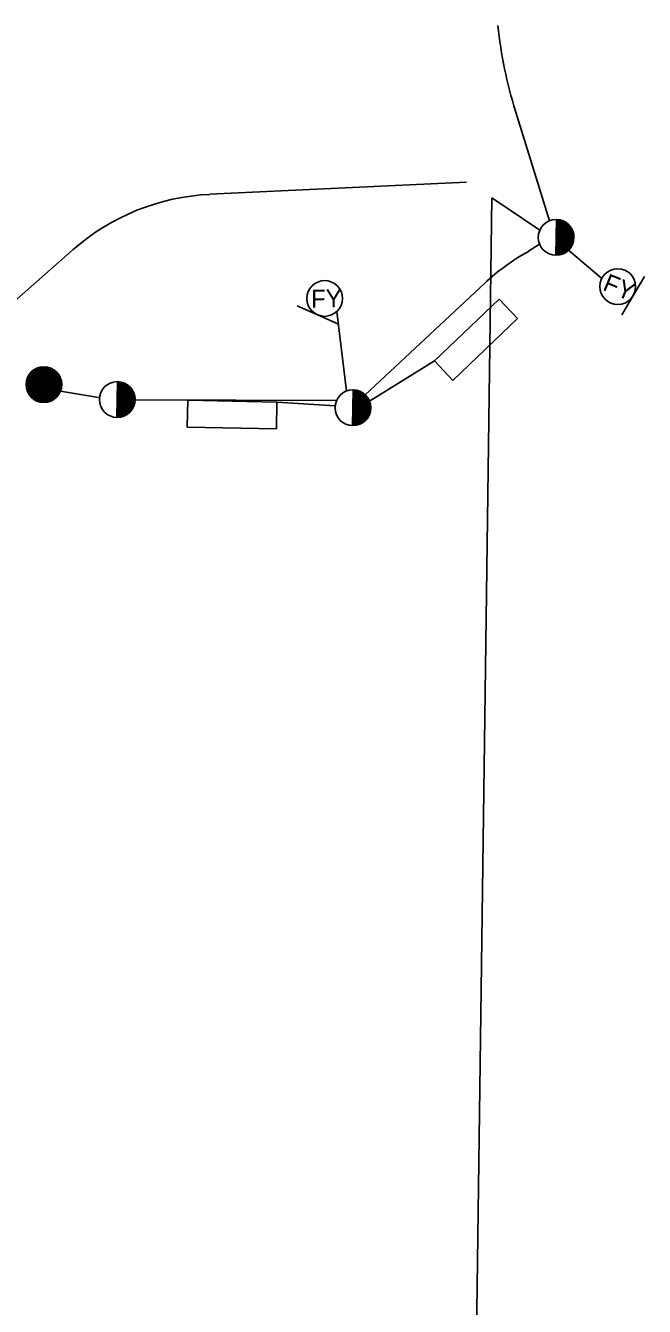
# Model space of a CAD drawing. Extents: x 584850 to 602551, y 145475 to 158627.
# Drawn here: x 585852.5 to 585991.1, y 152431.3 to 152717.9 of the extents above; entities that cross this region are included whole.
import ezdxf

# ---------------------------------------------------------------- set-up
doc = ezdxf.new("R2010")
doc.units = 0
doc.layers.add('Default', color=7, linetype='Continuous')

msp = doc.modelspace()

# ---------------------------------------------------------------- linework, layer by layer
at = {"layer": 'Default'}
for p, q in [((585969.85, 152674.27), (585962.21, 152698.81)), ((585893.76, 152680.19), (585951.25, 152682.9)), ((585953.46, 152423.71), (585956.91, 152679.38)), ((585967.65, 152672.15), (585956.91, 152679.38)), ((585971.39, 152674.55), (585971.24, 152666.55)), ((585971.32, 152671.23), (585973.83, 152673.64)), ((585971.33, 152671.57), (585973.64, 152673.8)), ((585971.34, 152672.25), (585973.22, 152674.05)), ((585971.34, 152671.91), (585973.43, 152673.93)), ((585971.35, 152672.59), (585973, 152674.17)), ((585971.36, 152673.27), (585972.5, 152674.36)), ((585971.36, 152672.93), (585972.75, 152674.27)), ((585971.37, 152673.6), (585972.23, 152674.43)), ((585975.2, 152669.62), (585971.37, 152673.6)), ((585971.38, 152674.28), (585971.64, 152674.53)), ((585971.38, 152673.94), (585971.94, 152674.49)), ((585975.29, 152670.22), (585971.38, 152674.28)), ((585975.25, 152669.92), (585971.38, 152673.94)), ((585971.39, 152674.55), (585971.39, 152674.55)), ((585971.39, 152674.55), (585971.39, 152674.55)), ((585975.3, 152670.56), (585971.46, 152674.54)), ((585975.29, 152670.92), (585971.83, 152674.51)), ((585975.22, 152671.34), (585972.24, 152674.43)), ((585975.1, 152671.81), (585972.72, 152674.28)), ((585974.83, 152672.44), (585973.34, 152673.98)), ((585971.24, 152666.82), (585975.29, 152670.72)), ((585971.25, 152667.5), (585975.22, 152671.32)), ((585971.25, 152667.16), (585975.28, 152671.04)), ((585971.26, 152667.84), (585975.17, 152671.6)), ((585971.27, 152668.51), (585974.99, 152672.09)), ((585971.27, 152668.17), (585975.08, 152671.85)), ((585971.28, 152668.85), (585974.89, 152672.33)), ((585971.29, 152669.53), (585974.64, 152672.76)), ((585971.29, 152669.19), (585974.76, 152672.54)), ((585971.3, 152669.87), (585974.5, 152672.95)), ((585971.31, 152670.55), (585974.19, 152673.32)), ((585971.31, 152670.21), (585974.34, 152673.14)), ((585971.32, 152670.89), (585974.01, 152673.49)), ((585974.4, 152668.03), (585971.32, 152671.23)), ((585974.25, 152667.84), (585971.32, 152670.89)), ((585974.55, 152668.22), (585971.33, 152671.57)), ((585974.81, 152668.65), (585971.34, 152672.25)), ((585974.69, 152668.42), (585971.34, 152671.91)), ((585974.93, 152668.87), (585971.35, 152672.59)), ((585975.12, 152669.37), (585971.36, 152673.27)), ((585975.03, 152669.11), (585971.36, 152672.93)), ((585833.35, 152641.7), (585863.13, 152667.83)), ((585972.35, 152666.7), (585971.26, 152667.84)), ((585972.85, 152666.88), (585971.27, 152668.51)), ((585972.62, 152666.77), (585971.27, 152668.17)), ((585973.09, 152666.98), (585971.28, 152668.85)), ((585973.51, 152667.23), (585971.29, 152669.53)), ((585973.31, 152667.09), (585971.29, 152669.19)), ((585973.72, 152667.36), (585971.3, 152669.87)), ((585974.08, 152667.68), (585971.31, 152670.55)), ((585973.9, 152667.52), (585971.31, 152670.21)), ((585971.32, 152666.56), (585975.3, 152670.4)), ((585971.69, 152666.58), (585975.26, 152670.02)), ((585972.09, 152666.64), (585975.21, 152669.64)), ((585972.56, 152666.75), (585975.05, 152669.15)), ((585973.17, 152667.01), (585974.75, 152668.54)), ((585971.48, 152666.57), (585971.24, 152666.82)), ((585971.28, 152666.55), (585971.24, 152666.6)), ((585972.08, 152666.64), (585971.25, 152667.5)), ((585971.8, 152666.59), (585971.25, 152667.16)), ((585974.09, 152667.67), (585981.55, 152661.37)), ((585986.03, 152653.2), (585991.09, 152661.83)), ((585944.05, 152642.9), (585958.52, 152656.71)), ((585958.52, 152656.71), (585962.66, 152652.37)), ((585913.27, 152655.25), (585922.41, 152651.2)), ((585924.32, 152636.15), (585922.19, 152653.95)), ((585948.19, 152638.56), (585962.66, 152652.37)), ((585944.05, 152642.9), (585929.5, 152633.89)), ((585944.05, 152642.9), (585948.19, 152638.56)), ((585852.56, 152637.62), (585856.39, 152641.61)), ((585852.58, 152637.29), (585856.72, 152641.6)), ((585852.58, 152637.99), (585856.02, 152641.57)), ((585852.61, 152636.98), (585857.03, 152641.58)), ((585852.62, 152638.38), (585855.62, 152641.5)), ((585852.67, 152636.7), (585857.32, 152641.53)), ((585852.74, 152636.42), (585857.59, 152641.47)), ((585852.76, 152638.87), (585855.16, 152641.37)), ((585852.83, 152636.17), (585857.85, 152641.4)), ((585858.24, 152634), (585852.87, 152639.16)), ((585852.94, 152635.93), (585858.09, 152641.3)), ((585858.46, 152634.12), (585852.98, 152639.38)), ((585853.03, 152639.5), (585854.55, 152641.08)), ((585853.05, 152635.7), (585858.32, 152641.2)), ((585858.68, 152634.25), (585853.09, 152639.61)), ((585853.18, 152635.49), (585858.54, 152641.08)), ((585858.89, 152634.38), (585853.22, 152639.82)), ((585853.31, 152635.28), (585858.75, 152640.94)), ((585859.07, 152634.53), (585853.36, 152640.01)), ((585853.46, 152635.09), (585858.95, 152640.81)), ((585859.26, 152634.69), (585853.5, 152640.21)), ((585853.62, 152634.91), (585859.14, 152640.66)), ((585859.43, 152634.85), (585853.67, 152640.38)), ((585853.78, 152634.74), (585859.31, 152640.49)), ((585859.59, 152635.04), (585853.84, 152640.55)), ((585853.97, 152634.58), (585859.49, 152640.33)), ((585859.74, 152635.22), (585854.02, 152640.71)), ((585854.16, 152634.43), (585859.64, 152640.14)), ((585859.88, 152635.42), (585854.22, 152640.85)), ((585854.35, 152634.28), (585859.79, 152639.95)), ((585860.01, 152635.63), (585854.42, 152640.99)), ((585854.56, 152634.16), (585859.93, 152639.75)), ((585860.13, 152635.84), (585854.64, 152641.12)), ((585854.78, 152634.04), (585860.05, 152639.53)), ((585860.23, 152636.08), (585854.87, 152641.23)), ((585855.01, 152633.93), (585860.17, 152639.31)), ((585860.32, 152636.33), (585855.1, 152641.34)), ((585860.41, 152636.58), (585855.36, 152641.42)), ((585860.46, 152636.86), (585855.63, 152641.5)), ((585860.52, 152637.14), (585855.91, 152641.56)), ((585860.53, 152637.45), (585856.22, 152641.59)), ((585860.54, 152637.78), (585856.55, 152641.61)), ((585860.5, 152638.15), (585856.92, 152641.59)), ((585860.44, 152638.54), (585857.33, 152641.53)), ((585860.28, 152639.02), (585857.79, 152641.42)), ((585859.99, 152639.64), (585858.41, 152641.16)), ((585856.88, 152633.64), (585852.56, 152637.79)), ((585856.54, 152633.63), (585852.57, 152637.45)), ((585857.19, 152633.68), (585852.59, 152638.09)), ((585856.19, 152633.64), (585852.59, 152637.1)), ((585857.47, 152633.74), (585852.63, 152638.39)), ((585855.78, 152633.7), (585852.68, 152636.68)), ((585857.75, 152633.81), (585852.7, 152638.65)), ((585857.99, 152633.9), (585852.78, 152638.91)), ((585855.26, 152633.85), (585860.27, 152639.07)), ((585855.51, 152633.76), (585860.35, 152638.81)), ((585855.79, 152633.7), (585860.44, 152638.55)), ((585856.08, 152633.66), (585860.49, 152638.25)), ((585856.38, 152633.63), (585860.53, 152637.95)), ((585856.72, 152633.64), (585860.54, 152637.61)), ((585857.08, 152633.66), (585860.53, 152637.26)), ((585857.48, 152633.74), (585860.46, 152636.84)), ((585857.96, 152633.89), (585860.34, 152636.37)), ((585873.06, 152638.27), (585872.91, 152630.27)), ((585872.96, 152633.25), (585876.31, 152636.47)), ((585872.96, 152632.91), (585876.43, 152636.26)), ((585872.97, 152633.59), (585876.17, 152636.67)), ((585872.98, 152634.27), (585875.86, 152637.04)), ((585872.98, 152633.93), (585876.01, 152636.86)), ((585872.99, 152634.61), (585875.68, 152637.2)), ((585873, 152635.29), (585875.31, 152637.51)), ((585873, 152634.95), (585875.5, 152637.36)), ((585873.01, 152635.96), (585874.89, 152637.77)), ((585873.01, 152635.63), (585875.1, 152637.64)), ((585873.02, 152636.3), (585874.67, 152637.89)), ((585876.6, 152632.59), (585873.02, 152636.3)), ((585873.03, 152636.98), (585874.17, 152638.08)), ((585873.03, 152636.64), (585874.42, 152637.99)), ((585876.79, 152633.08), (585873.03, 152636.98)), ((585876.7, 152632.83), (585873.03, 152636.64)), ((585873.04, 152637.32), (585873.9, 152638.15)), ((585876.87, 152633.34), (585873.04, 152637.32)), ((585873.05, 152638), (585873.31, 152638.25)), ((585873.05, 152637.66), (585873.61, 152638.21)), ((585876.96, 152633.94), (585873.05, 152638)), ((585876.92, 152633.64), (585873.05, 152637.66)), ((585873.06, 152638.27), (585873.06, 152638.27)), ((585873.06, 152638.27), (585873.06, 152638.27)), ((585876.97, 152634.28), (585873.13, 152638.26)), ((585876.96, 152634.64), (585873.5, 152638.23)), ((585876.89, 152635.06), (585873.91, 152638.15)), ((585876.77, 152635.53), (585874.39, 152638)), ((585876.5, 152636.15), (585875.01, 152637.7)), ((585925.86, 152636.43), (585925.71, 152628.43)), ((585925.84, 152635.82), (585926.41, 152636.36)), ((585925.84, 152635.48), (585926.7, 152636.31)), ((585925.85, 152636.16), (585926.11, 152636.41)), ((585925.86, 152636.43), (585925.86, 152636.42)), ((585925.86, 152636.43), (585925.86, 152636.42)), ((585929.77, 152632.44), (585925.93, 152636.42)), ((585929.76, 152632.79), (585926.3, 152636.39)), ((585929.69, 152633.21), (585926.71, 152636.31)), ((585855.29, 152633.84), (585852.82, 152636.21)), ((585854.66, 152634.11), (585853.11, 152635.6)), ((585858.58, 152634.19), (585860.07, 152635.74)), ((585860.28, 152636.16), (585868.82, 152634.72)), ((585872.91, 152630.54), (585876.97, 152634.44)), ((585872.92, 152630.87), (585876.95, 152634.76)), ((585872.93, 152631.55), (585876.84, 152635.32)), ((585872.93, 152631.21), (585876.89, 152635.04)), ((585872.94, 152632.23), (585876.66, 152635.81)), ((585872.94, 152631.89), (585876.75, 152635.57)), ((585872.95, 152632.57), (585876.56, 152636.05)), ((585875.39, 152631.08), (585872.97, 152633.59)), ((585875.75, 152631.4), (585872.98, 152634.27)), ((585875.57, 152631.23), (585872.98, 152633.93)), ((585875.92, 152631.56), (585872.99, 152634.61)), ((585872.99, 152630.27), (585876.97, 152634.11)), ((585876.22, 152631.94), (585873, 152635.29)), ((585876.07, 152631.75), (585873, 152634.95)), ((585876.48, 152632.36), (585873.01, 152635.96)), ((585876.37, 152632.14), (585873.01, 152635.63)), ((585873.36, 152630.3), (585876.93, 152633.74)), ((585922.11, 152634.03), (585876.98, 152634.19)), ((585888.77, 152634.11), (585888.65, 152628.11)), ((585888.77, 152634.11), (585908.76, 152633.71)), ((585908.76, 152633.71), (585908.65, 152627.71)), ((585908.76, 152633.71), (585921.81, 152632.88)), ((585925.73, 152629.71), (585929.64, 152633.47)), ((585925.74, 152630.39), (585929.46, 152633.97)), ((585925.74, 152630.05), (585929.55, 152633.73)), ((585925.75, 152630.73), (585929.36, 152634.21)), ((585925.76, 152631.41), (585929.11, 152634.63)), ((585925.76, 152631.07), (585929.23, 152634.42)), ((585925.77, 152632.09), (585928.81, 152635.01)), ((585925.77, 152631.75), (585928.97, 152634.83)), ((585925.78, 152632.43), (585928.66, 152635.2)), ((585925.79, 152633.11), (585928.3, 152635.52)), ((585925.79, 152632.77), (585928.48, 152635.36)), ((585925.8, 152633.44), (585928.11, 152635.67)), ((585929.02, 152630.1), (585925.8, 152633.44)), ((585925.81, 152634.12), (585927.69, 152635.93)), ((585925.81, 152633.78), (585927.9, 152635.8)), ((585929.28, 152630.52), (585925.81, 152634.12)), ((585929.16, 152630.3), (585925.81, 152633.78)), ((585925.82, 152634.46), (585927.47, 152636.05)), ((585929.4, 152630.74), (585925.82, 152634.46)), ((585925.83, 152635.14), (585926.97, 152636.24)), ((585925.83, 152634.8), (585927.22, 152636.14)), ((585929.59, 152631.24), (585925.83, 152635.14)), ((585929.5, 152630.98), (585925.83, 152634.8)), ((585929.72, 152631.8), (585925.84, 152635.82)), ((585929.67, 152631.5), (585925.84, 152635.48)), ((585929.76, 152632.1), (585925.85, 152636.16)), ((585929.57, 152633.69), (585927.19, 152636.16)), ((585929.3, 152634.31), (585927.81, 152635.86)), ((585873.15, 152630.29), (585872.91, 152630.54)), ((585873.47, 152630.31), (585872.92, 152630.87)), ((585874.02, 152630.42), (585872.93, 152631.55)), ((585873.75, 152630.35), (585872.93, 152631.21)), ((585874.52, 152630.59), (585872.94, 152632.23)), ((585874.29, 152630.49), (585872.94, 152631.89)), ((585874.76, 152630.69), (585872.95, 152632.57)), ((585875.18, 152630.95), (585872.96, 152633.25)), ((585874.98, 152630.81), (585872.96, 152632.91)), ((585873.77, 152630.36), (585876.88, 152633.35)), ((585874.23, 152630.47), (585876.72, 152632.87)), ((585874.84, 152630.73), (585876.43, 152632.25)), ((585925.71, 152628.69), (585929.76, 152632.6)), ((585925.72, 152629.37), (585929.69, 152633.19)), ((585925.72, 152629.03), (585929.75, 152632.91)), ((585927.56, 152628.85), (585925.75, 152630.73)), ((585927.98, 152629.1), (585925.76, 152631.41)), ((585927.78, 152628.97), (585925.76, 152631.07)), ((585928.37, 152629.39), (585925.77, 152632.09)), ((585928.19, 152629.24), (585925.77, 152631.75)), ((585928.55, 152629.56), (585925.78, 152632.43)), ((585928.87, 152629.91), (585925.79, 152633.11)), ((585928.72, 152629.72), (585925.79, 152632.77)), ((585925.79, 152628.43), (585929.77, 152632.27)), ((585926.16, 152628.46), (585929.73, 152631.9)), ((585926.56, 152628.52), (585929.67, 152631.51)), ((585927.03, 152628.63), (585929.52, 152631.03)), ((585872.95, 152630.27), (585872.91, 152630.31)), ((585888.65, 152628.11), (585908.65, 152627.71)), ((585925.95, 152628.44), (585925.71, 152628.69)), ((585925.75, 152628.43), (585925.71, 152628.47)), ((585926.55, 152628.51), (585925.72, 152629.37)), ((585926.27, 152628.46), (585925.72, 152629.03)), ((585926.82, 152628.58), (585925.73, 152629.71)), ((585927.32, 152628.75), (585925.74, 152630.39)), ((585927.09, 152628.65), (585925.74, 152630.05)), ((585927.64, 152628.89), (585929.22, 152630.41))]:
    msp.add_line(p, q, dxfattribs=at)
for points in [[(585965.11, 152667.43), (585967.61, 152669.03)], [(585928.53, 152635.33), (585955.25, 152660.26)]]:
    msp.add_lwpolyline(points, dxfattribs=at)
for centre in [(585971.31, 152670.55), (585985.11, 152659.54), (585919.46, 152656.88), (585856.55, 152637.62), (585872.98, 152634.27), (585925.78, 152632.43)]:
    msp.add_circle(centre, 4, dxfattribs=at)
for centre, radius, start, end in [((586057.69, 152728.55), 100, 186.0885, 197.2983), ((585896.11, 152630.24), 50, 92.6965, 131.2654), ((585971.31, 152670.55), 4, 268.9257, 88.9257), ((585989.35, 152623.7), 50, 119.0039, 133.0137), ((585872.98, 152634.27), 4, 268.9257, 88.9257), ((585925.78, 152632.43), 4, 268.9257, 88.9257)]:
    msp.add_arc(centre, radius, start, end, dxfattribs=at)

# ---------------------------------------------------------------- texts
for rotation, p in [(337.5188, (585981.52, 152658.86)), (0.6202, (585916.43, 152654.85))]:
    msp.add_text('FY', height=4, rotation=rotation, dxfattribs=at).set_placement(p)

doc.saveas('drawing.dxf')
